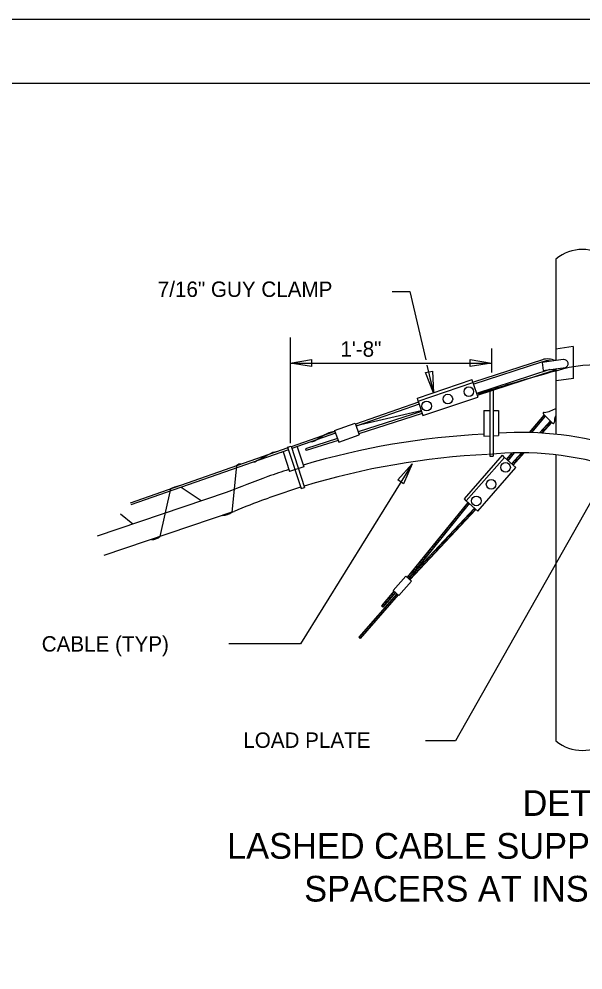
# Model space of a CAD drawing. Extents: x 1299104.8 to 1299141.6, y 239639.8 to 239661.8.
# Drawn here: x 1299126.82 to 1299131.21, y 239654.39 to 239661.79 of the extents above; entities that cross this region are included whole.
import ezdxf

# ---------------------------------------------------------------- set-up
doc = ezdxf.new("R2010")
doc.units = 0
for name, color, linetype in [('DIM TXT', 7, 'Continuous'), ('GS_plotshape_p', 7, 'Continuous'), ('Level 1', 7, 'Continuous')]:
    doc.layers.add(name, color=color, linetype=linetype)

msp = doc.modelspace()

# ---------------------------------------------------------------- linework, layer by layer
at = {"layer": 'DIM TXT'}
for p, q in [((1299130.9993, 239659.9223), (1299130.9993, 239659.1326)), ((1299129.7249, 239659.669), (1299129.8611, 239659.669)), ((1299129.8611, 239659.669), (1299129.9856, 239659.1385)), ((1299128.9303, 239659.3124), (1299128.9303, 239658.4888)), ((1299130.4977, 239659.2257), (1299130.4977, 239659.0395)), ((1299130.9993, 239659.2249), (1299131.1335, 239659.2437)), ((1299131.1345, 239659.2423), (1299131.1345, 239658.9925)), ((1299130.8934, 239659.1392), (1299130.3563, 239658.963)), ((1299130.8864, 239659.1211), (1299130.3611, 239658.9488)), ((1299131.055, 239659.1399), (1299130.8919, 239659.1186)), ((1299130.8919, 239659.1186), (1299130.9002, 239659.0555)), ((1299128.9303, 239659.1124), (1299130.4977, 239659.1124)), ((1299129.9952, 239659.0973), (1299130.0457, 239658.8821)), ((1299130.9523, 239659.0623), (1299130.3811, 239658.875)), ((1299130.974, 239659.0536), (1299130.3859, 239658.8608)), ((1299130.9002, 239659.0555), (1299131.0731, 239659.078)), ((1299130.9993, 239659.0649), (1299130.9993, 239658.5584)), ((1299129.922, 239658.8404), (1299130.3484, 239658.9842)), ((1299130.0189, 239658.9965), (1299130.0457, 239658.8821)), ((1299130.3521, 239658.9612), (1299130.3484, 239658.9842)), ((1299131.1348, 239658.9927), (1299131.0009, 239658.9739)), ((1299129.9256, 239658.8175), (1299130.3521, 239658.9612)), ((1299130.3521, 239658.9612), (1299130.3904, 239658.8475)), ((1299130.365, 239658.9257), (1299130.364, 239658.9261)), ((1299130.484, 239658.9005), (1299130.484, 239658.3875)), ((1299130.5104, 239658.9088), (1299130.5104, 239658.3889)), ((1299129.9256, 239658.8175), (1299129.922, 239658.8404)), ((1299129.964, 239658.7038), (1299130.3904, 239658.8475)), ((1299129.9286, 239658.8083), (1299129.439, 239658.6369)), ((1299129.9337, 239658.7942), (1299129.4441, 239658.6228)), ((1299129.9256, 239658.8175), (1299129.964, 239658.7038)), ((1299129.9512, 239658.7418), (1299129.4449, 239658.6231)), ((1299129.9536, 239658.7348), (1299129.4605, 239658.5769)), ((1299129.9583, 239658.7205), (1299129.4656, 239658.5628)), ((1299130.4368, 239658.7447), (1299130.484, 239658.7447)), ((1299130.4368, 239658.7447), (1299130.4368, 239658.5442)), ((1299130.5104, 239658.7447), (1299130.5522, 239658.7447)), ((1299130.5522, 239658.7447), (1299130.5522, 239658.5492)), ((1299130.7922, 239658.5723), (1299130.9072, 239658.7084)), ((1299130.8114, 239658.5717), (1299130.9187, 239658.6987)), ((1299130.8981, 239658.6744), (1299130.877, 239658.6726)), ((1299130.9078, 239658.6859), (1299130.8867, 239658.6841)), ((1299130.9175, 239658.6973), (1299130.8963, 239658.6955)), ((1299130.9014, 239658.7158), (1299130.9731, 239658.6451)), ((1299129.2768, 239658.5878), (1299129.4361, 239658.645)), ((1299129.4361, 239658.645), (1299129.4684, 239658.5551)), ((1299131.6262, 239658.662), (1299130.2172, 239656.1718)), ((1299130.84, 239658.6057), (1299130.8189, 239658.6039)), ((1299130.8497, 239658.6171), (1299130.8286, 239658.6153)), ((1299130.8594, 239658.6286), (1299130.8383, 239658.6268)), ((1299130.8691, 239658.64), (1299130.8479, 239658.6383)), ((1299130.8788, 239658.6515), (1299130.8576, 239658.6497)), ((1299130.8884, 239658.6629), (1299130.8673, 239658.6612)), ((1299130.8716, 239658.569), (1299130.9561, 239658.6621)), ((1299130.8908, 239658.5678), (1299130.9666, 239658.6513)), ((1299130.9245, 239658.6049), (1299130.9033, 239658.6039)), ((1299130.9346, 239658.616), (1299130.9134, 239658.615)), ((1299130.9446, 239658.6271), (1299130.9235, 239658.6261)), ((1299130.9547, 239658.6382), (1299130.9335, 239658.6372)), ((1299130.9643, 239658.6487), (1299130.9431, 239658.6476)), ((1299129.2793, 239658.5809), (1299128.9392, 239658.4618)), ((1299129.2843, 239658.5668), (1299128.9438, 239658.4476)), ((1299129.2992, 239658.5253), (1299129.0504, 239658.4456)), ((1299129.1997, 239658.5545), (1299129.1206, 239658.5052)), ((1299129.2326, 239658.5688), (1299129.1997, 239658.5545)), ((1299129.2741, 239658.5791), (1299129.2326, 239658.5688)), ((1299129.2768, 239658.5878), (1299129.3091, 239658.4979)), ((1299129.3091, 239658.4979), (1299129.4684, 239658.5551)), ((1299130.4368, 239658.5442), (1299130.484, 239658.5462)), ((1299130.5104, 239658.5474), (1299130.5522, 239658.5492)), ((1299130.8207, 239658.5827), (1299130.7995, 239658.581)), ((1299130.8304, 239658.5942), (1299130.8092, 239658.5924)), ((1299130.8943, 239658.5716), (1299130.8731, 239658.5705)), ((1299130.9043, 239658.5827), (1299130.8832, 239658.5816)), ((1299130.9144, 239658.5938), (1299130.8932, 239658.5928)), ((1299128.9129, 239658.4526), (1299127.6863, 239658.0231)), ((1299128.9111, 239658.4581), (1299128.9378, 239658.4661)), ((1299128.9111, 239658.4581), (1299129.0152, 239658.1357)), ((1299128.9378, 239658.4661), (1299129.0417, 239658.1442)), ((1299128.9858, 239658.46), (1299129.0362, 239658.304)), ((1299129.3043, 239658.5112), (1299129.055, 239658.4313)), ((1299129.1041, 239658.4996), (1299129.0839, 239658.4966)), ((1299129.1206, 239658.5052), (1299129.1041, 239658.4996)), ((1299128.9175, 239658.4383), (1299127.6913, 239658.0089)), ((1299128.7755, 239658.4057), (1299128.6776, 239658.3543)), ((1299128.7937, 239658.4164), (1299128.7755, 239658.4057)), ((1299128.8125, 239658.4181), (1299128.7937, 239658.4164)), ((1299128.8222, 239658.4209), (1299128.8125, 239658.4181)), ((1299128.8646, 239658.4176), (1299128.8503, 239658.4137)), ((1299128.8759, 239658.4215), (1299128.9254, 239658.268)), ((1299129.0504, 239658.4456), (1299129.055, 239658.4313)), ((1299130.2869, 239658.0573), (1299130.5833, 239658.3958)), ((1299130.3016, 239658.0392), (1299130.598, 239658.3778)), ((1299130.484, 239658.3875), (1299130.5104, 239658.3889)), ((1299130.598, 239658.3778), (1299130.5833, 239658.3958)), ((1299130.598, 239658.3778), (1299130.6883, 239658.2988)), ((1299130.615, 239658.3626), (1299130.6576, 239658.4131)), ((1299130.6464, 239658.3765), (1299130.6253, 239658.3747)), ((1299130.6265, 239658.3529), (1299130.6776, 239658.4135)), ((1299130.6561, 239658.388), (1299130.6349, 239658.3862)), ((1299130.6658, 239658.3994), (1299130.6446, 239658.3977)), ((1299130.654, 239658.3289), (1299130.731, 239658.4139)), ((1299130.6754, 239658.4109), (1299130.6543, 239658.4091)), ((1299130.6652, 239658.319), (1299130.7511, 239658.4137)), ((1299130.723, 239658.3827), (1299130.7018, 239658.3816)), ((1299130.7331, 239658.3938), (1299130.7119, 239658.3927)), ((1299130.7431, 239658.4049), (1299130.7219, 239658.4038)), ((1299130.9993, 239658.3981), (1299130.9993, 239656.1723)), ((1299128.513, 239658.3126), (1299128.4767, 239657.9521)), ((1299128.5306, 239658.3253), (1299128.513, 239658.3126)), ((1299128.5602, 239658.3285), (1299128.5306, 239658.3253)), ((1299128.6556, 239658.3427), (1299128.6462, 239658.341)), ((1299128.6776, 239658.3543), (1299128.6556, 239658.3427)), ((1299129.0362, 239658.304), (1299128.9254, 239658.2682)), ((1299129.8806, 239658.3286), (1299129.0116, 239656.9266)), ((1299130.6367, 239658.3651), (1299130.6156, 239658.3633)), ((1299130.627, 239658.3536), (1299130.626, 239658.3535)), ((1299130.6726, 239658.3271), (1299130.6571, 239658.3263)), ((1299130.6827, 239658.3382), (1299130.6615, 239658.3372)), ((1299130.6928, 239658.3493), (1299130.6716, 239658.3483)), ((1299130.7028, 239658.3604), (1299130.6816, 239658.3594)), ((1299130.7129, 239658.3715), (1299130.6917, 239658.3705)), ((1299130.3919, 239657.9602), (1299130.6883, 239658.2988)), ((1299128.0658, 239658.156), (1299128.0296, 239658.1463)), ((1299128.4325, 239658.1054), (1299127.4293, 239657.7663)), ((1299127.9998, 239658.1329), (1299127.9164, 239657.7627)), ((1299128.0296, 239658.1463), (1299127.9998, 239658.1329)), ((1299128.238, 239658.0397), (1299128.0813, 239658.1455)), ((1299129.0152, 239658.1357), (1299129.0417, 239658.1442)), ((1299128.739, 239658.0541), (1299128.7653, 239658.0636)), ((1299130.313, 239658.0285), (1299129.8417, 239657.4451)), ((1299130.3247, 239658.0191), (1299129.8533, 239657.4356)), ((1299130.3016, 239658.0392), (1299130.2869, 239658.0573)), ((1299130.2953, 239658.0065), (1299130.3162, 239658.0085)), ((1299130.3016, 239658.0392), (1299130.3919, 239657.9602)), ((1299130.3045, 239658.018), (1299130.3254, 239658.02)), ((1299128.4836, 239657.9544), (1299127.4804, 239657.6153)), ((1299127.7051, 239657.8595), (1299127.6098, 239657.937)), ((1299128.4767, 239657.9521), (1299128.4938, 239657.9583)), ((1299130.3646, 239657.9837), (1299129.8515, 239657.4367)), ((1299130.3756, 239657.9734), (1299129.8624, 239657.4264)), ((1299130.2397, 239657.9378), (1299130.2606, 239657.9398)), ((1299130.249, 239657.9492), (1299130.2699, 239657.9512)), ((1299130.2582, 239657.9607), (1299130.2792, 239657.9627)), ((1299130.2675, 239657.9721), (1299130.2884, 239657.9742)), ((1299130.2767, 239657.9836), (1299130.2977, 239657.9856)), ((1299130.286, 239657.995), (1299130.3069, 239657.9971)), ((1299130.323, 239657.9392), (1299130.3441, 239657.9399)), ((1299130.3332, 239657.9502), (1299130.3544, 239657.9508)), ((1299130.3435, 239657.9611), (1299130.3646, 239657.9617)), ((1299130.3537, 239657.972), (1299130.3749, 239657.9727)), ((1299128.4064, 239657.9259), (1299128.404, 239657.9275)), ((1299130.1749, 239657.8576), (1299130.1958, 239657.8596)), ((1299130.1842, 239657.869), (1299130.2051, 239657.871)), ((1299130.1934, 239657.8805), (1299130.2144, 239657.8825)), ((1299130.2027, 239657.8919), (1299130.2236, 239657.894)), ((1299130.2119, 239657.9034), (1299130.2329, 239657.9054)), ((1299130.2212, 239657.9148), (1299130.2421, 239657.9169)), ((1299130.2305, 239657.9263), (1299130.2514, 239657.9283)), ((1299130.2512, 239657.8628), (1299130.2724, 239657.8634)), ((1299130.2615, 239657.8737), (1299130.2827, 239657.8743)), ((1299130.2717, 239657.8846), (1299130.2929, 239657.8853)), ((1299130.282, 239657.8955), (1299130.3031, 239657.8962)), ((1299130.2922, 239657.9065), (1299130.3134, 239657.9071)), ((1299130.3025, 239657.9174), (1299130.3236, 239657.918)), ((1299130.3127, 239657.9283), (1299130.3339, 239657.929)), ((1299130.1194, 239657.7888), (1299130.1403, 239657.7908)), ((1299130.1286, 239657.8003), (1299130.1496, 239657.8023)), ((1299130.1379, 239657.8117), (1299130.1588, 239657.8138)), ((1299130.1472, 239657.8232), (1299130.1681, 239657.8252)), ((1299130.1575, 239657.836), (1299130.1784, 239657.838)), ((1299130.1663, 239657.8468), (1299130.1872, 239657.8489)), ((1299130.1795, 239657.7863), (1299130.2007, 239657.7869)), ((1299130.1897, 239657.7972), (1299130.2109, 239657.7979)), ((1299130.2, 239657.8082), (1299130.2212, 239657.8088)), ((1299130.2102, 239657.8191), (1299130.2314, 239657.8197)), ((1299130.2205, 239657.83), (1299130.2417, 239657.8306)), ((1299130.2307, 239657.8409), (1299130.2519, 239657.8416)), ((1299130.241, 239657.8519), (1299130.2622, 239657.8525)), ((1299130.0622, 239657.718), (1299130.0826, 239657.7194)), ((1299130.0731, 239657.7315), (1299130.094, 239657.7336)), ((1299130.0824, 239657.743), (1299130.1033, 239657.745)), ((1299130.0916, 239657.7544), (1299130.1125, 239657.7565)), ((1299130.1009, 239657.7659), (1299130.1218, 239657.7679)), ((1299130.1077, 239657.7098), (1299130.1289, 239657.7105)), ((1299130.1103, 239657.7775), (1299130.1312, 239657.7795)), ((1299130.118, 239657.7208), (1299130.1392, 239657.7214)), ((1299130.1282, 239657.7317), (1299130.1494, 239657.7323)), ((1299130.1385, 239657.7426), (1299130.1597, 239657.7433)), ((1299130.1487, 239657.7535), (1299130.1699, 239657.7542)), ((1299130.159, 239657.7645), (1299130.1802, 239657.7651)), ((1299130.1692, 239657.7754), (1299130.1904, 239657.776)), ((1299129.999, 239657.6401), (1299130.02, 239657.6415)), ((1299130.0083, 239657.6513), (1299130.0292, 239657.6534)), ((1299130.0176, 239657.6628), (1299130.0385, 239657.6648)), ((1299130.0268, 239657.6742), (1299130.0478, 239657.6763)), ((1299130.0361, 239657.6857), (1299130.057, 239657.6877)), ((1299130.0453, 239657.6972), (1299130.0663, 239657.6992)), ((1299130.0462, 239657.6443), (1299130.0674, 239657.6449)), ((1299130.0532, 239657.7069), (1299130.0736, 239657.7083)), ((1299130.0565, 239657.6552), (1299130.0777, 239657.6559)), ((1299130.0667, 239657.6661), (1299130.0879, 239657.6668)), ((1299130.077, 239657.6771), (1299130.0982, 239657.6777)), ((1299130.0872, 239657.688), (1299130.1084, 239657.6886)), ((1299130.0975, 239657.6989), (1299130.1187, 239657.6996)), ((1299129.9364, 239657.5622), (1299129.9567, 239657.5636)), ((1299129.9453, 239657.5734), (1299129.9657, 239657.5747)), ((1299129.9543, 239657.5845), (1299129.9747, 239657.5858)), ((1299129.9633, 239657.5956), (1299129.9837, 239657.597)), ((1299129.9723, 239657.6068), (1299129.9912, 239657.608)), ((1299129.9737, 239657.5657), (1299129.9949, 239657.5671)), ((1299129.9813, 239657.6179), (1299130.0008, 239657.6192)), ((1299129.9848, 239657.5779), (1299130.006, 239657.5793)), ((1299129.9903, 239657.629), (1299130.0104, 239657.6303)), ((1299129.9951, 239657.5886), (1299130.0163, 239657.59)), ((1299130.0062, 239657.5997), (1299130.0273, 239657.6011)), ((1299130.016, 239657.611), (1299130.0372, 239657.6124)), ((1299130.0259, 239657.6223), (1299130.047, 239657.6237)), ((1299130.0357, 239657.6336), (1299130.0569, 239657.635)), ((1299129.8824, 239657.4955), (1299129.9028, 239657.4968)), ((1299129.8914, 239657.5066), (1299129.9118, 239657.5079)), ((1299129.8997, 239657.4874), (1299129.9209, 239657.4888)), ((1299129.9004, 239657.5177), (1299129.9208, 239657.5191)), ((1299129.9094, 239657.5288), (1299129.9298, 239657.5302)), ((1299129.9102, 239657.4986), (1299129.9313, 239657.5)), ((1299129.9184, 239657.54), (1299129.9387, 239657.5413)), ((1299129.9194, 239657.5093), (1299129.9405, 239657.5107)), ((1299129.9274, 239657.5511), (1299129.9477, 239657.5525)), ((1299129.931, 239657.5209), (1299129.9521, 239657.5223)), ((1299129.9426, 239657.5326), (1299129.9638, 239657.534)), ((1299129.9531, 239657.5444), (1299129.9742, 239657.5458)), ((1299129.9628, 239657.5546), (1299129.9839, 239657.556)), ((1299129.8302, 239657.4552), (1299129.7314, 239657.3423)), ((1299129.8753, 239657.4156), (1299129.7765, 239657.3028)), ((1299129.8302, 239657.4552), (1299129.8753, 239657.4156)), ((1299129.8464, 239657.4509), (1299129.8668, 239657.4523)), ((1299129.8554, 239657.4621), (1299129.8758, 239657.4634)), ((1299129.8562, 239657.4324), (1299129.8688, 239657.4332)), ((1299129.8605, 239657.4433), (1299129.8794, 239657.4446)), ((1299129.8644, 239657.4732), (1299129.8848, 239657.4745)), ((1299129.8703, 239657.4546), (1299129.8915, 239657.456)), ((1299129.8734, 239657.4843), (1299129.8938, 239657.4857)), ((1299129.8802, 239657.4659), (1299129.9013, 239657.4673)), ((1299129.8894, 239657.4761), (1299129.9105, 239657.4775)), ((1299129.7314, 239657.3423), (1299129.7765, 239657.3028)), ((1299129.7597, 239657.3175), (1299129.4638, 239656.9785)), ((1299129.771, 239657.3076), (1299129.4751, 239656.9686)), ((1299129.738, 239657.3365), (1299129.6403, 239657.2227)), ((1299129.7493, 239657.3266), (1299129.6516, 239657.2128)), ((1299129.679, 239657.2678), (1299129.7, 239657.2692)), ((1299129.6887, 239657.2791), (1299129.7097, 239657.2805)), ((1299129.6984, 239657.2903), (1299129.7194, 239657.2917)), ((1299129.7081, 239657.3016), (1299129.7291, 239657.303)), ((1299129.7178, 239657.3129), (1299129.7388, 239657.3143)), ((1299129.7199, 239657.2719), (1299129.7411, 239657.2733)), ((1299129.7275, 239657.3242), (1299129.7484, 239657.3256)), ((1299129.7298, 239657.2832), (1299129.7509, 239657.2846)), ((1299129.7396, 239657.2944), (1299129.7608, 239657.2959)), ((1299129.7495, 239657.3057), (1299129.7706, 239657.3071)), ((1299129.6403, 239657.2227), (1299129.6612, 239657.2241)), ((1299129.6403, 239657.2227), (1299129.6516, 239657.2128)), ((1299129.65, 239657.234), (1299129.6709, 239657.2354)), ((1299129.651, 239657.1929), (1299129.6721, 239657.1943)), ((1299129.6596, 239657.2452), (1299129.6806, 239657.2466)), ((1299129.6608, 239657.2042), (1299129.682, 239657.2056)), ((1299129.6693, 239657.2565), (1299129.6903, 239657.2579)), ((1299129.6707, 239657.2155), (1299129.6918, 239657.2169)), ((1299129.6805, 239657.2267), (1299129.7017, 239657.2281)), ((1299129.6904, 239657.238), (1299129.7115, 239657.2394)), ((1299129.7002, 239657.2493), (1299129.7214, 239657.2507)), ((1299129.7101, 239657.2606), (1299129.7312, 239657.262)), ((1299129.5919, 239657.1252), (1299129.613, 239657.1266)), ((1299129.6017, 239657.1365), (1299129.6228, 239657.1379)), ((1299129.6116, 239657.1477), (1299129.6327, 239657.1492)), ((1299129.6214, 239657.159), (1299129.6426, 239657.1604)), ((1299129.6313, 239657.1703), (1299129.6524, 239657.1717)), ((1299129.6411, 239657.1816), (1299129.6623, 239657.183)), ((1299129.5229, 239657.0462), (1299129.544, 239657.0476)), ((1299129.5327, 239657.0575), (1299129.5539, 239657.0589)), ((1299129.5426, 239657.0688), (1299129.5637, 239657.0702)), ((1299129.5525, 239657.08), (1299129.5736, 239657.0814)), ((1299129.5623, 239657.0913), (1299129.5834, 239657.0927)), ((1299129.5722, 239657.1026), (1299129.5933, 239657.104)), ((1299129.582, 239657.1139), (1299129.6031, 239657.1153)), ((1299129.4638, 239656.9785), (1299129.4849, 239656.9799)), ((1299129.4638, 239656.9785), (1299129.4849, 239656.9799)), ((1299129.4638, 239656.9785), (1299129.4751, 239656.9686)), ((1299129.4736, 239656.9898), (1299129.4948, 239656.9912)), ((1299129.4835, 239657.0011), (1299129.5046, 239657.0025)), ((1299129.4933, 239657.0123), (1299129.5145, 239657.0137)), ((1299129.5032, 239657.0236), (1299129.5243, 239657.025)), ((1299129.513, 239657.0349), (1299129.5342, 239657.0363)), ((1299129.0116, 239656.9266), (1299128.4529, 239656.9266)), ((1299130.2172, 239656.1718), (1299129.984, 239656.1718))]:
    msp.add_line(p, q, dxfattribs=at)
for points in [[(1299129.0971, 239659.1396), (1299129.0971, 239659.0852), (1299128.9303, 239659.1124)], [(1299130.3309, 239659.0852), (1299130.3309, 239659.1396), (1299130.4977, 239659.1124)], [(1299129.9847, 239659.0398), (1299130.0379, 239659.051), (1299130.0457, 239658.8821)], [(1299129.8137, 239658.1734), (1299129.7679, 239658.2027), (1299129.8806, 239658.3286)]]:
    msp.add_lwpolyline(points, close=True, dxfattribs=at)
for centre in [(1299130.3213, 239658.8904), (1299130.1579, 239658.8326), (1299129.9936, 239658.7786), (1299130.607, 239658.3011), (1299130.4948, 239658.169), (1299130.3799, 239658.0398)]:
    msp.add_circle(centre, 0.0375, dxfattribs=at)
for centre, radius, start, end in [((1299131.2055, 239659.6762), 0.3211, 50.03379, 129.96621), ((1299130.9337, 239658.9961), 0.1336, 79.15862, 110.71471), ((1299130.9337, 239658.9961), 0.1486, 66.04524, 105.73196), ((1299131.062, 239659.108), 0.032, 285.31813, 97.41971), ((1299134.3207, 239646.7728), 12.7202, 105.14601, 107.97566), ((1299130.9042, 239659.2438), 0.2026, 290.14184, 300.61386), ((1299131.3088, 239658.0608), 1.0381, 60.22849, 107.47221), ((1299130.8676, 239658.9929), 0.2675, 278.69853, 300.45445), ((1299130.9066, 239658.7211), 0.0075, 78.76641, 225.41178), ((1299131.1622, 239658.6431), 0.1766, 160.99955, 177.51359), ((1299130.9783, 239658.6504), 0.00751, 225.51106, 2.53402), ((1299130.7369, 239652.5776), 5.9889, 92.87239, 106.54461), ((1299130.7213, 239655.96), 2.6133, 72.24591, 93.70981), ((1299130.7369, 239652.5776), 5.8295, 92.66509, 106.93847), ((1299130.7213, 239655.96), 2.4539, 72.24591, 95.77175), ((1299133.4362, 239645.5327), 13.5318, 110.22766, 111.70164), ((1299130.7369, 239652.5776), 5.9889, 107.65923, 109.29924), ((1299130.7369, 239652.5776), 5.8295, 107.21246, 109.76853), ((1299130.7369, 239652.5776), 5.8295, 110.04266, 112.63005), ((1299128.3915, 239658.073), 0.1479, 275.77365, 305.18221), ((1299127.8621, 239657.8158), 0.076, 261.70796, 315.65064), ((1299131.2055, 239656.4184), 0.3211, 230.03379, 309.96621)]:
    msp.add_arc(centre, radius, start, end, dxfattribs=at)
at = {"layer": 'GS_plotshape_p'}
msp.add_lwpolyline([(1299104.8019, 239661.7913), (1299138.8019, 239661.7913), (1299138.8019, 239639.7913), (1299104.8019, 239639.7913)], close=True, dxfattribs=at)
at = {"layer": 'Level 1'}
msp.add_lwpolyline([(1299138.3019, 239640.2913), (1299106.3019, 239640.2913), (1299106.3019, 239661.2913), (1299138.3019, 239661.2913)], close=True, dxfattribs=at)

# ---------------------------------------------------------------- texts
at = {"layer": 'DIM TXT'}
for s, height, p in [('7/16" GUY CLAMP', 0.12, (1299127.9002, 239659.6278)), ('1\'-8"', 0.12, (1299129.3215, 239659.1624)), ('CABLE (TYP)', 0.12, (1299126.997, 239656.8668)), ('LOAD PLATE', 0.12, (1299128.5659, 239656.1174)), ('DETAIL D', 0.2, (1299130.739, 239655.5877)), ('LASHED CABLE SUPPORTS AND CABLE ', 0.2, (1299128.4398, 239655.2543)), ('SPACERS AT INSIDE CORNERS', 0.2, (1299129.0398, 239654.921))]:
    msp.add_text(s, height=height, dxfattribs=at).set_placement(p)

doc.saveas('drawing.dxf')
